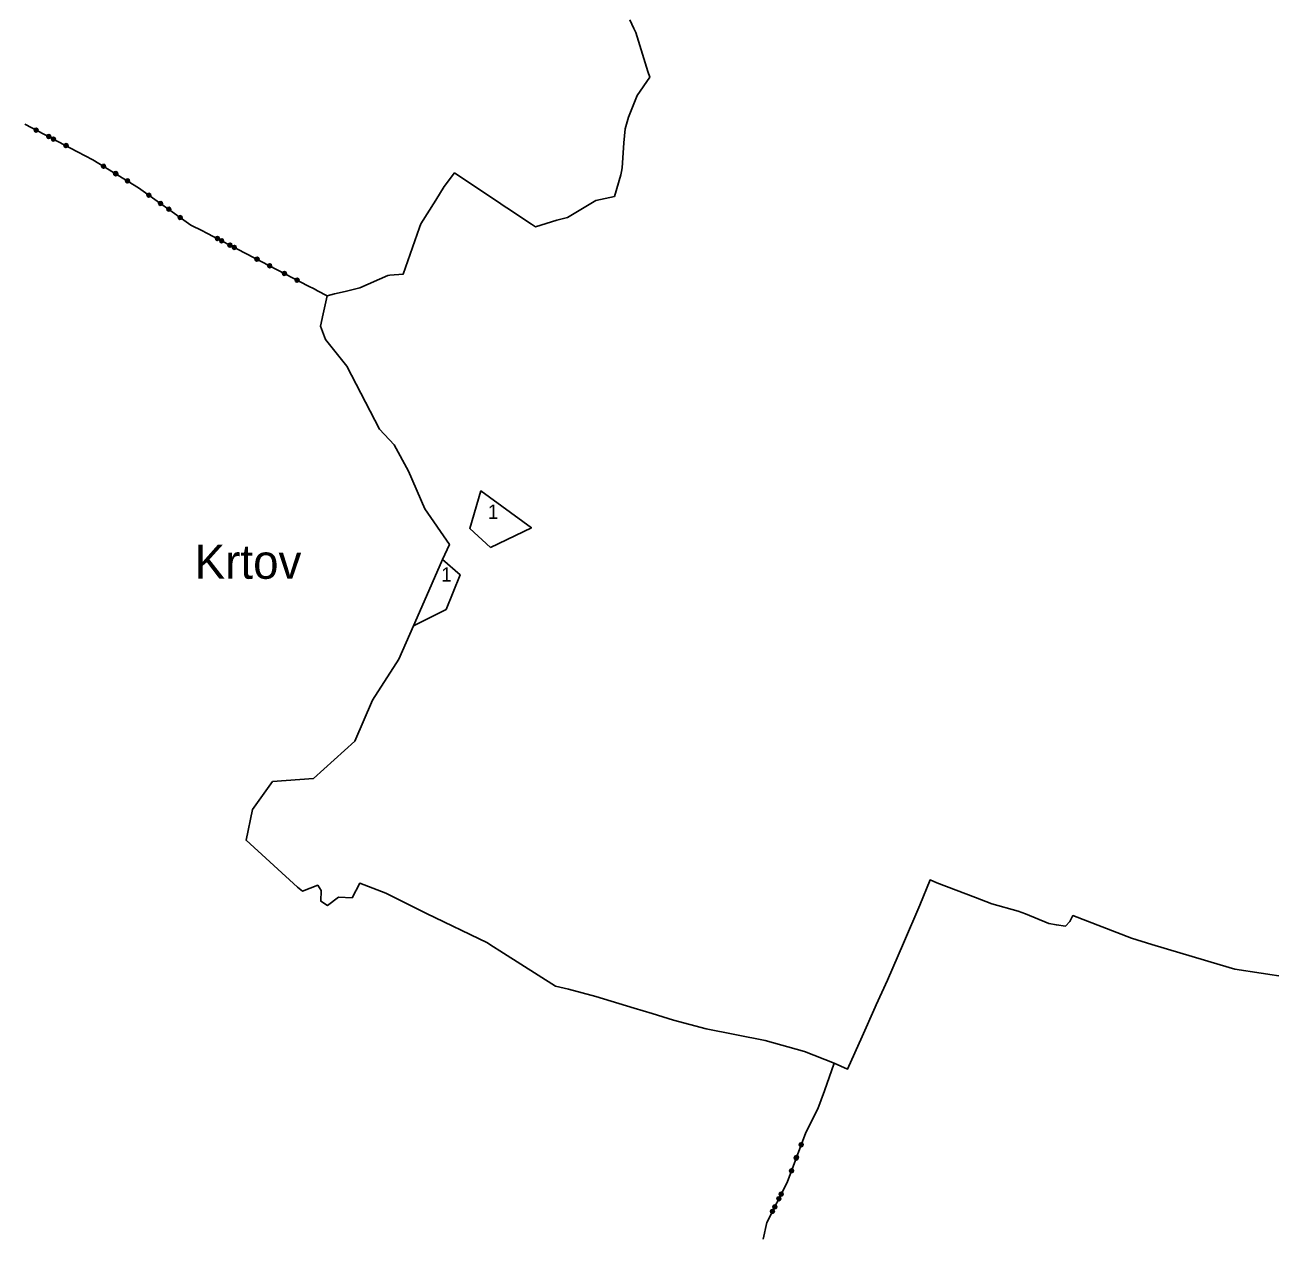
# Model space of a CAD drawing. Extents: x -723521 to -719353, y -1129324 to -1125791.
# Drawn here: x -723521 to -722428, y -1129015 to -1127949 of the extents above; entities that cross this region are included whole.
import ezdxf

# ---------------------------------------------------------------- set-up
doc = ezdxf.new("R2010")
doc.units = 0
for name, color, linetype in [('HRA_KU', 7, 'Continuous'), ('KU_OST', 7, 'Continuous'), ('NERES_SET', 7, 'Continuous'), ('OVNE_SET', 7, 'Continuous'), ('OZN', 7, 'Continuous')]:
    doc.layers.add(name, color=color, linetype=linetype)

msp = doc.modelspace()

# ---------------------------------------------------------------- linework, layer by layer
at = {"layer": 'HRA_KU'}
for points in [[(-723255.3, -1128186.4), (-723263.9, -1128182), (-723266.9, -1128180.4), (-723271.6, -1128177.9), (-723326.7, -1128149.3), (-723361.6, -1128131.1), (-723364.8, -1128129.5), (-723375, -1128124.5), (-723420.8, -1128091.7), (-723460.9, -1128067), (-723474.4, -1128060), (-723520.6, -1128035.8)], [(-723512.2, -1128042), (-723512.6, -1128040.7), (-723512, -1128039.6), (-723510.7, -1128039.2), (-723509.5, -1128039.8), (-723509.1, -1128041.1), (-723509.7, -1128042.3), (-723511, -1128042.7), (-723512.2, -1128042), (-723512, -1128041.9), (-723510.9, -1128042.5), (-723510.4, -1128042.3), (-723512.2, -1128041.4), (-723512.3, -1128040.8), (-723509.8, -1128042.1), (-723509.7, -1128041.8), (-723512.1, -1128040.5), (-723511.9, -1128040.1), (-723509.5, -1128041.4), (-723509.3, -1128041.1), (-723511.8, -1128039.8), (-723511.2, -1128039.6), (-723509.5, -1128040.5), (-723509.6, -1128040), (-723510.7, -1128039.4)], [(-723501.1, -1128047.8), (-723501.5, -1128046.5), (-723500.9, -1128045.3), (-723499.6, -1128044.9), (-723498.4, -1128045.6), (-723498, -1128046.8), (-723498.7, -1128048), (-723499.9, -1128048.4), (-723501.1, -1128047.8), (-723501, -1128047.7), (-723499.9, -1128048.2), (-723499.4, -1128048.1), (-723501.2, -1128047.1), (-723501.3, -1128046.6), (-723498.8, -1128047.9), (-723498.7, -1128047.5), (-723501.1, -1128046.2), (-723501, -1128045.9), (-723498.5, -1128047.2), (-723498.3, -1128046.8), (-723500.8, -1128045.5), (-723500.2, -1128045.4), (-723498.5, -1128046.3), (-723498.6, -1128045.7), (-723499.7, -1128045.2)], [(-723497, -1128050), (-723497.4, -1128048.7), (-723496.8, -1128047.5), (-723495.5, -1128047.1), (-723494.3, -1128047.7), (-723493.9, -1128049), (-723494.5, -1128050.2), (-723495.8, -1128050.6), (-723497, -1128050), (-723496.8, -1128049.9), (-723495.7, -1128050.4), (-723495.2, -1128050.2), (-723497, -1128049.3), (-723497.1, -1128048.8), (-723494.7, -1128050.1), (-723494.5, -1128049.7), (-723497, -1128048.4), (-723496.8, -1128048.1), (-723494.3, -1128049.4), (-723494.1, -1128049), (-723496.6, -1128047.7), (-723496, -1128047.5), (-723494.3, -1128048.5), (-723494.4, -1128047.9), (-723495.5, -1128047.4)], [(-723485.9, -1128055.8), (-723486.4, -1128054.5), (-723485.7, -1128053.3), (-723484.4, -1128052.9), (-723483.2, -1128053.5), (-723482.8, -1128054.8), (-723483.5, -1128056), (-723484.8, -1128056.4), (-723485.9, -1128055.8), (-723485.8, -1128055.6), (-723484.7, -1128056.2), (-723484.2, -1128056), (-723486, -1128055.1), (-723486.2, -1128054.5), (-723483.7, -1128055.8), (-723483.5, -1128055.5), (-723486, -1128054.2), (-723485.8, -1128053.8), (-723483.3, -1128055.1), (-723483.1, -1128054.8), (-723485.6, -1128053.5), (-723485.1, -1128053.3), (-723483.3, -1128054.2), (-723483.5, -1128053.7), (-723484.5, -1128053.1)], [(-723452.9, -1128073.8), (-723453.3, -1128072.5), (-723452.5, -1128071.3), (-723451.2, -1128071), (-723450.1, -1128071.7), (-723449.8, -1128073.1), (-723450.5, -1128074.2), (-723451.8, -1128074.5), (-723452.9, -1128073.8), (-723452.7, -1128073.7), (-723451.7, -1128074.3), (-723451.1, -1128074.2), (-723452.8, -1128073.2), (-723453, -1128072.6), (-723450.6, -1128074.1), (-723450.4, -1128073.7), (-723452.8, -1128072.3), (-723452.6, -1128071.9), (-723450.2, -1128073.4), (-723450, -1128073.1), (-723452.3, -1128071.6), (-723451.8, -1128071.5), (-723450.1, -1128072.5), (-723450.2, -1128072), (-723451.2, -1128071.3)], [(-723442.6, -1128080.1), (-723442.9, -1128078.8), (-723442.2, -1128077.7), (-723440.9, -1128077.4), (-723439.8, -1128078.1), (-723439.5, -1128079.4), (-723440.2, -1128080.5), (-723441.5, -1128080.9), (-723442.6, -1128080.1), (-723442.4, -1128080.1), (-723441.4, -1128080.7), (-723440.8, -1128080.6), (-723442.5, -1128079.5), (-723442.7, -1128079), (-723440.3, -1128080.4), (-723440.1, -1128080.1), (-723442.5, -1128078.6), (-723442.2, -1128078.3), (-723439.9, -1128079.7), (-723439.6, -1128079.4), (-723442, -1128077.9), (-723441.5, -1128077.8), (-723439.8, -1128078.8), (-723439.9, -1128078.3), (-723440.9, -1128077.7)], [(-723442.3, -1128080.4), (-723442.6, -1128079), (-723441.9, -1128077.9), (-723440.6, -1128077.6), (-723439.4, -1128078.3), (-723439.1, -1128079.6), (-723439.8, -1128080.8), (-723441.1, -1128081.1), (-723442.3, -1128080.4), (-723442.1, -1128080.2), (-723441.1, -1128080.8), (-723440.6, -1128080.7), (-723442.3, -1128079.7), (-723442.4, -1128079.1), (-723440, -1128080.6), (-723439.8, -1128080.2), (-723442.2, -1128078.8), (-723442, -1128078.4), (-723439.6, -1128079.9), (-723439.4, -1128079.6), (-723441.8, -1128078.1), (-723441.2, -1128078), (-723439.5, -1128079), (-723439.7, -1128078.5), (-723440.7, -1128077.8)], [(-723432, -1128086.7), (-723432.3, -1128085.4), (-723431.6, -1128084.2), (-723430.3, -1128083.9), (-723429.1, -1128084.6), (-723428.8, -1128085.9), (-723429.5, -1128087.1), (-723430.8, -1128087.4), (-723432, -1128086.7), (-723431.8, -1128086.6), (-723430.8, -1128087.2), (-723430.3, -1128087.1), (-723432, -1128086), (-723432.1, -1128085.5), (-723429.7, -1128086.9), (-723429.5, -1128086.6), (-723431.9, -1128085.1), (-723431.7, -1128084.8), (-723429.3, -1128086.2), (-723429.1, -1128085.9), (-723431.5, -1128084.4), (-723430.9, -1128084.3), (-723429.2, -1128085.3), (-723429.4, -1128084.8), (-723430.4, -1128084.2)], [(-723413.3, -1128099), (-723413.5, -1128097.7), (-723412.7, -1128096.6), (-723411.4, -1128096.4), (-723410.3, -1128097.2), (-723410.1, -1128098.5), (-723410.9, -1128099.6), (-723412.2, -1128099.8), (-723413.3, -1128099), (-723413.1, -1128098.9), (-723412.1, -1128099.6), (-723411.5, -1128099.6), (-723413.2, -1128098.4), (-723413.3, -1128097.8), (-723411, -1128099.5), (-723410.7, -1128099.1), (-723413, -1128097.5), (-723412.8, -1128097.2), (-723410.5, -1128098.8), (-723410.3, -1128098.5), (-723412.6, -1128096.9), (-723412, -1128096.8), (-723410.4, -1128097.9), (-723410.5, -1128097.4), (-723411.4, -1128096.7)], [(-723403.1, -1128106.3), (-723403.4, -1128105), (-723402.6, -1128103.9), (-723401.3, -1128103.6), (-723400.2, -1128104.4), (-723399.9, -1128105.8), (-723400.7, -1128106.9), (-723402, -1128107.1), (-723403.1, -1128106.3), (-723403, -1128106.2), (-723402, -1128106.9), (-723401.5, -1128106.8), (-723403.1, -1128105.6), (-723403.2, -1128105), (-723400.9, -1128106.7), (-723400.7, -1128106.3), (-723402.9, -1128104.7), (-723402.7, -1128104.4), (-723400.4, -1128106), (-723400.2, -1128105.7), (-723402.5, -1128104.1), (-723401.9, -1128104), (-723400.3, -1128105.1), (-723400.4, -1128104.6), (-723401.4, -1128103.9)], [(-723395.9, -1128111.4), (-723396.2, -1128110.1), (-723395.4, -1128109), (-723394.1, -1128108.8), (-723393, -1128109.6), (-723392.7, -1128110.9), (-723393.5, -1128112), (-723394.8, -1128112.2), (-723395.9, -1128111.4), (-723395.7, -1128111.4), (-723394.7, -1128112.1), (-723394.2, -1128112), (-723395.8, -1128110.8), (-723395.9, -1128110.2), (-723393.6, -1128111.9), (-723393.4, -1128111.5), (-723395.7, -1128109.9), (-723395.4, -1128109.6), (-723393.1, -1128111.2), (-723392.9, -1128110.9), (-723395.2, -1128109.3), (-723394.6, -1128109.2), (-723393, -1128110.3), (-723393.1, -1128109.8), (-723394.1, -1128109.1)], [(-723385.8, -1128118.7), (-723386, -1128117.4), (-723385.2, -1128116.3), (-723383.9, -1128116.1), (-723382.8, -1128116.8), (-723382.6, -1128118.2), (-723383.4, -1128119.3), (-723384.7, -1128119.5), (-723385.8, -1128118.7), (-723385.6, -1128118.6), (-723384.6, -1128119.3), (-723384.1, -1128119.2), (-723385.7, -1128118), (-723385.8, -1128117.5), (-723383.5, -1128119.1), (-723383.3, -1128118.8), (-723385.6, -1128117.1), (-723385.3, -1128116.8), (-723383.1, -1128118.4), (-723382.8, -1128118.1), (-723385.1, -1128116.5), (-723384.5, -1128116.4), (-723382.9, -1128117.5), (-723383, -1128117), (-723384, -1128116.3)], [(-723353.1, -1128137.3), (-723353.5, -1128136), (-723352.9, -1128134.8), (-723351.6, -1128134.4), (-723350.4, -1128135.1), (-723350, -1128136.3), (-723350.6, -1128137.5), (-723351.9, -1128138), (-723353.1, -1128137.3), (-723352.9, -1128137.2), (-723351.8, -1128137.8), (-723351.3, -1128137.6), (-723353.1, -1128136.7), (-723353.2, -1128136.1), (-723350.7, -1128137.4), (-723350.6, -1128137.1), (-723353, -1128135.8), (-723352.9, -1128135.4), (-723350.4, -1128136.7), (-723350.2, -1128136.4), (-723352.7, -1128135.1), (-723352.1, -1128134.9), (-723350.4, -1128135.8), (-723350.5, -1128135.3), (-723351.6, -1128134.7)], [(-723349.3, -1128139.3), (-723349.7, -1128138), (-723349.1, -1128136.8), (-723347.8, -1128136.4), (-723346.6, -1128137.1), (-723346.2, -1128138.3), (-723346.8, -1128139.5), (-723348.1, -1128139.9), (-723349.3, -1128139.3), (-723349.1, -1128139.2), (-723348, -1128139.8), (-723347.5, -1128139.6), (-723349.2, -1128138.7), (-723349.4, -1128138.1), (-723346.9, -1128139.4), (-723346.7, -1128139.1), (-723349.2, -1128137.8), (-723349, -1128137.4), (-723346.6, -1128138.7), (-723346.4, -1128138.4), (-723348.9, -1128137.1), (-723348.3, -1128136.9), (-723346.5, -1128137.8), (-723346.7, -1128137.3), (-723347.8, -1128136.7)], [(-723342, -1128143.1), (-723342.4, -1128141.8), (-723341.8, -1128140.6), (-723340.5, -1128140.2), (-723339.3, -1128140.8), (-723338.9, -1128142.1), (-723339.5, -1128143.3), (-723340.8, -1128143.7), (-723342, -1128143.1), (-723341.9, -1128142.9), (-723340.8, -1128143.5), (-723340.3, -1128143.3), (-723342.1, -1128142.4), (-723342.2, -1128141.9), (-723339.7, -1128143.2), (-723339.6, -1128142.8), (-723342, -1128141.5), (-723341.9, -1128141.2), (-723339.4, -1128142.4), (-723339.2, -1128142.1), (-723341.7, -1128140.8), (-723341.1, -1128140.6), (-723339.4, -1128141.6), (-723339.5, -1128141), (-723340.6, -1128140.5)], [(-723338.2, -1128145.1), (-723338.6, -1128143.8), (-723338, -1128142.6), (-723336.7, -1128142.2), (-723335.5, -1128142.8), (-723335.1, -1128144.1), (-723335.7, -1128145.3), (-723337, -1128145.7), (-723338.2, -1128145.1), (-723338.1, -1128144.9), (-723337, -1128145.5), (-723336.5, -1128145.3), (-723338.2, -1128144.4), (-723338.4, -1128143.8), (-723335.9, -1128145.1), (-723335.7, -1128144.8), (-723338.2, -1128143.5), (-723338, -1128143.1), (-723335.6, -1128144.4), (-723335.4, -1128144.1), (-723337.9, -1128142.8), (-723337.3, -1128142.6), (-723335.5, -1128143.5), (-723335.7, -1128143), (-723336.8, -1128142.4)], [(-723318.2, -1128155.5), (-723318.7, -1128154.2), (-723318, -1128153), (-723316.7, -1128152.6), (-723315.6, -1128153.2), (-723315.1, -1128154.5), (-723315.8, -1128155.7), (-723317.1, -1128156.1), (-723318.2, -1128155.5), (-723318, -1128155.4), (-723317, -1128155.9), (-723316.4, -1128155.7), (-723318.2, -1128154.8), (-723318.4, -1128154.3), (-723315.9, -1128155.6), (-723315.7, -1128155.2), (-723318.2, -1128153.9), (-723318, -1128153.6), (-723315.5, -1128154.9), (-723315.3, -1128154.5), (-723317.8, -1128153.2), (-723317.3, -1128153), (-723315.5, -1128154), (-723315.7, -1128153.4), (-723316.7, -1128152.9)], [(-723307.2, -1128161.2), (-723307.6, -1128160), (-723306.9, -1128158.8), (-723305.7, -1128158.4), (-723304.5, -1128159), (-723304.1, -1128160.3), (-723304.7, -1128161.5), (-723306, -1128161.9), (-723307.2, -1128161.2), (-723307, -1128161.1), (-723306, -1128161.6), (-723305.4, -1128161.5), (-723307.2, -1128160.5), (-723307.4, -1128160), (-723304.9, -1128161.3), (-723304.7, -1128160.9), (-723307.2, -1128159.6), (-723307, -1128159.3), (-723304.5, -1128160.6), (-723304.3, -1128160.2), (-723306.8, -1128158.9), (-723306.3, -1128158.8), (-723304.5, -1128159.7), (-723304.7, -1128159.2), (-723305.7, -1128158.6)], [(-723294.2, -1128168), (-723294.6, -1128166.7), (-723294, -1128165.5), (-723292.7, -1128165.1), (-723291.5, -1128165.7), (-723291.1, -1128167), (-723291.7, -1128168.2), (-723293, -1128168.6), (-723294.2, -1128168), (-723294, -1128167.9), (-723292.9, -1128168.4), (-723292.4, -1128168.3), (-723294.1, -1128167.3), (-723294.3, -1128166.8), (-723291.8, -1128168.1), (-723291.6, -1128167.7), (-723294.1, -1128166.4), (-723293.9, -1128166.1), (-723291.5, -1128167.4), (-723291.3, -1128167), (-723293.8, -1128165.7), (-723293.2, -1128165.6), (-723291.4, -1128166.5), (-723291.6, -1128166), (-723292.7, -1128165.4)], [(-723283.1, -1128173.8), (-723283.5, -1128172.5), (-723282.9, -1128171.3), (-723281.6, -1128170.9), (-723280.4, -1128171.5), (-723280, -1128172.8), (-723280.6, -1128174), (-723281.9, -1128174.4), (-723283.1, -1128173.8), (-723283, -1128173.6), (-723281.9, -1128174.2), (-723281.4, -1128174), (-723283.1, -1128173.1), (-723283.3, -1128172.5), (-723280.8, -1128173.8), (-723280.6, -1128173.5), (-723283.1, -1128172.2), (-723282.9, -1128171.8), (-723280.5, -1128173.1), (-723280.3, -1128172.8), (-723282.8, -1128171.5), (-723282.2, -1128171.3), (-723280.4, -1128172.2), (-723280.6, -1128171.7), (-723281.7, -1128171.1)], [(-722810.5, -1128860), (-722818.9, -1128884.5), (-722824.7, -1128900.2), (-722835.3, -1128920.9), (-722851.6, -1128964.9), (-722869.6, -1129000.1), (-722872.8, -1129014.5)], [(-722838, -1128932.8), (-722839.2, -1128933.4), (-722840.5, -1128932.9), (-722841.1, -1128931.7), (-722840.6, -1128930.4), (-722839.4, -1128929.9), (-722838.1, -1128930.3), (-722837.6, -1128931.6), (-722838, -1128932.8), (-722838.2, -1128932.7), (-722837.8, -1128931.6), (-722838, -1128931.1), (-722838.7, -1128932.9), (-722839.2, -1128933.2), (-722838.2, -1128930.5), (-722838.6, -1128930.4), (-722839.6, -1128933), (-722840, -1128932.9), (-722839, -1128930.3), (-722839.4, -1128930.1), (-722840.3, -1128932.8), (-722840.6, -1128932.2), (-722839.9, -1128930.4), (-722840.4, -1128930.6), (-722840.8, -1128931.7)], [(-722842.4, -1128944.5), (-722843.6, -1128945.1), (-722844.9, -1128944.6), (-722845.4, -1128943.4), (-722844.9, -1128942.1), (-722843.7, -1128941.6), (-722842.5, -1128942.1), (-722841.9, -1128943.3), (-722842.4, -1128944.5), (-722842.5, -1128944.3), (-722842.1, -1128943.2), (-722842.3, -1128942.7), (-722843, -1128944.6), (-722843.5, -1128944.8), (-722842.6, -1128942.2), (-722842.9, -1128942), (-722843.9, -1128944.7), (-722844.3, -1128944.5), (-722843.3, -1128941.9), (-722843.7, -1128941.8), (-722844.7, -1128944.4), (-722844.9, -1128943.9), (-722844.2, -1128942), (-722844.7, -1128942.2), (-722845.1, -1128943.4)], [(-722842.2, -1128944), (-722843.4, -1128944.6), (-722844.7, -1128944.1), (-722845.2, -1128942.9), (-722844.8, -1128941.6), (-722843.5, -1128941.1), (-722842.3, -1128941.5), (-722841.7, -1128942.7), (-722842.2, -1128944), (-722842.3, -1128943.9), (-722841.9, -1128942.8), (-722842.2, -1128942.3), (-722842.9, -1128944.1), (-722843.4, -1128944.4), (-722842.4, -1128941.7), (-722842.8, -1128941.6), (-722843.7, -1128944.2), (-722844.1, -1128944.1), (-722843.1, -1128941.5), (-722843.5, -1128941.3), (-722844.5, -1128944), (-722844.7, -1128943.4), (-722844, -1128941.6), (-722844.6, -1128941.8), (-722845, -1128942.9)], [(-722846.5, -1128955.7), (-722847.7, -1128956.3), (-722849, -1128955.8), (-722849.6, -1128954.6), (-722849.1, -1128953.3), (-722847.9, -1128952.8), (-722846.6, -1128953.2), (-722846.1, -1128954.5), (-722846.5, -1128955.7), (-722846.7, -1128955.5), (-722846.2, -1128954.4), (-722846.5, -1128953.9), (-722847.2, -1128955.8), (-722847.7, -1128956), (-722846.7, -1128953.4), (-722847.1, -1128953.2), (-722848.1, -1128955.9), (-722848.4, -1128955.7), (-722847.5, -1128953.1), (-722847.8, -1128953), (-722848.8, -1128955.6), (-722849, -1128955.1), (-722848.4, -1128953.2), (-722848.9, -1128953.4), (-722849.3, -1128954.5)], [(-722857.8, -1128980.4), (-722859, -1128980.8), (-722860.2, -1128980.2), (-722860.7, -1128979), (-722860, -1128977.7), (-722858.8, -1128977.3), (-722857.6, -1128977.9), (-722857.2, -1128979.2), (-722857.8, -1128980.4), (-722857.9, -1128980.3), (-722857.4, -1128979.2), (-722857.6, -1128978.7), (-722858.5, -1128980.5), (-722859, -1128980.6), (-722857.7, -1128978.1), (-722858.1, -1128978), (-722859.4, -1128980.5), (-722859.7, -1128980.3), (-722858.4, -1128977.8), (-722858.8, -1128977.6), (-722860.1, -1128980.1), (-722860.2, -1128979.6), (-722859.3, -1128977.8), (-722859.9, -1128978), (-722860.4, -1128979)], [(-722855.7, -1128976.4), (-722857, -1128976.8), (-722858.2, -1128976.2), (-722858.6, -1128974.9), (-722858, -1128973.7), (-722856.7, -1128973.3), (-722855.5, -1128973.9), (-722855.1, -1128975.2), (-722855.7, -1128976.4), (-722855.9, -1128976.3), (-722855.3, -1128975.2), (-722855.5, -1128974.7), (-722856.4, -1128976.5), (-722857, -1128976.6), (-722855.7, -1128974.1), (-722856, -1128974), (-722857.3, -1128976.5), (-722857.7, -1128976.3), (-722856.4, -1128973.8), (-722856.7, -1128973.6), (-722858, -1128976.1), (-722858.2, -1128975.6), (-722857.3, -1128973.8), (-722857.8, -1128973.9), (-722858.4, -1128975)], [(-722863.5, -1128991.6), (-722864.7, -1128992), (-722865.9, -1128991.4), (-722866.4, -1128990.1), (-722865.7, -1128988.9), (-722864.5, -1128988.5), (-722863.3, -1128989.1), (-722862.8, -1128990.4), (-722863.5, -1128991.6), (-722863.6, -1128991.3), (-722863, -1128990.3), (-722863.2, -1128989.7), (-722864.1, -1128991.5), (-722864.6, -1128991.7), (-722863.4, -1128989.2), (-722863.7, -1128989), (-722865, -1128991.5), (-722865.4, -1128991.3), (-722864.1, -1128988.8), (-722864.4, -1128988.6), (-722865.7, -1128991.1), (-722865.9, -1128990.6), (-722865, -1128988.8), (-722865.5, -1128989), (-722866.1, -1128990.1)], [(-722861.4, -1128987.6), (-722862.7, -1128988), (-722863.9, -1128987.4), (-722864.3, -1128986.1), (-722863.7, -1128984.9), (-722862.4, -1128984.5), (-722861.2, -1128985.1), (-722860.8, -1128986.4), (-722861.4, -1128987.6), (-722861.5, -1128987.3), (-722861, -1128986.3), (-722861.1, -1128985.7), (-722862.1, -1128987.5), (-722862.6, -1128987.7), (-722861.3, -1128985.2), (-722861.7, -1128985), (-722863, -1128987.5), (-722863.3, -1128987.3), (-722862, -1128984.8), (-722862.4, -1128984.6), (-722863.7, -1128987.1), (-722863.8, -1128986.6), (-722862.9, -1128984.8), (-722863.5, -1128985), (-722864, -1128986.1)]]:
    msp.add_lwpolyline(points, dxfattribs=at)
at = {"layer": 'NERES_SET'}
for points in [[(-723112.1, -1128407.4), (-723130.2, -1128390.7), (-723120.4, -1128357.8), (-723076.1, -1128390.1), (-723112.1, -1128407.4)], [(-723154, -1128418), (-723138.7, -1128431.3), (-723151, -1128462), (-723179.6, -1128476.2)]]:
    msp.add_lwpolyline(points, dxfattribs=at)
at = {"layer": 'OVNE_SET'}
msp.add_lwpolyline([(-722989.7, -1127944.1), (-722986.2, -1127951.8), (-722984.5, -1127955.4), (-722973.8, -1127989.5), (-722972.2, -1127994.6), (-722983.3, -1128010.8), (-722990.9, -1128029.7), (-722993.7, -1128039.9), (-722995, -1128052.1), (-722996.6, -1128074.2), (-722996.9, -1128077.3), (-722997.7, -1128080.2), (-723003.2, -1128099.2), (-723019.5, -1128102.8), (-723044.5, -1128117.7), (-723053.7, -1128120.2), (-723072.6, -1128125.8), (-723075.9, -1128123.6), (-723097.7, -1128109.2), (-723099, -1128108.3), (-723103, -1128105.7), (-723143.6, -1128078.6), (-723152.7, -1128090.6), (-723160.1, -1128102.5), (-723173.2, -1128123.4), (-723174.3, -1128126.6), (-723188.8, -1128167.6), (-723200.3, -1128168.5), (-723202, -1128168.6), (-723226.8, -1128179.4), (-723239.7, -1128182.6), (-723248.9, -1128184.8), (-723249, -1128184.9), (-723255.3, -1128186.4), (-723258.9, -1128202.4), (-723261.3, -1128213.2), (-723256.7, -1128224.8), (-723245.1, -1128239.4), (-723238.1, -1128248.3), (-723209.5, -1128303.7), (-723196.7, -1128317.4), (-723184.1, -1128340.3), (-723169.6, -1128373.6), (-723148.1, -1128404.7), (-723154, -1128418), (-723172.4, -1128459.4), (-723179.6, -1128476.2), (-723192.4, -1128505.6), (-723215.7, -1128541.4), (-723231.1, -1128577.3), (-723267.4, -1128610.1), (-723303.2, -1128612.8), (-723320.9, -1128637.5), (-723326.5, -1128664.4), (-723281.4, -1128705.7), (-723277, -1128709), (-723263.6, -1128703.9), (-723260.6, -1128708.6), (-723260.8, -1128717.9), (-723255, -1128721.6), (-723245.3, -1128714.5), (-723233.5, -1128714.9), (-723226.7, -1128702.2), (-723203.9, -1128710.8), (-723168.2, -1128728.8), (-723114.6, -1128754.5), (-723112.6, -1128755.8), (-723100.7, -1128763.4), (-723054.9, -1128792.6), (-723043.7, -1128795.2), (-723019.7, -1128801.6), (-722999.5, -1128807.7), (-722985.9, -1128811.9), (-722970.1, -1128816.6), (-722951.4, -1128822.3), (-722922.8, -1128829.9), (-722871.1, -1128840.1), (-722836.5, -1128849.8), (-722810.5, -1128860), (-722798.8, -1128865.4), (-722785.9, -1128836.7), (-722774.3, -1128810.8), (-722773.5, -1128809), (-722763.5, -1128787.2), (-722749.5, -1128754.7), (-722735.3, -1128721.5), (-722726.2, -1128699.3), (-722720.2, -1128701.7), (-722686.5, -1128714.7), (-722671.9, -1128720.1), (-722649, -1128726.8), (-722642.5, -1128729), (-722622.1, -1128737.5), (-722615.4, -1128738.8), (-722607.3, -1128739.8), (-722603.7, -1128735.8), (-722600.8, -1128730.5), (-722549.5, -1128750.3), (-722531.5, -1128756), (-722471.7, -1128773.7), (-722458.9, -1128777.7), (-722412.5, -1128784.5)], dxfattribs=at)

# ---------------------------------------------------------------- texts
at = {"layer": 'KU_OST'}
msp.add_text('Krtov', height=30, dxfattribs=at).set_placement((-723371.6, -1128434.9))
at = {"layer": 'OZN'}
for p in [(-723114.4, -1128382.3), (-723155.4, -1128437.4)]:
    msp.add_text('1', height=12.5, dxfattribs=at).set_placement(p)

doc.saveas('drawing.dxf')
